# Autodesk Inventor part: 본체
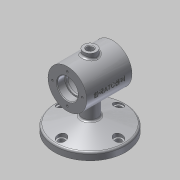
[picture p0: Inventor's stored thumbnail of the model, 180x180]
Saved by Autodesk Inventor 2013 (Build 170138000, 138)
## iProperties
Created: 2018-12
Part Number: 본체
Material: 알루미늄 6061
Document SubType Name: Modeling
Designer: Gpr
Density: 2.71 g/cm^3
Mass: 687.623 g
Surface Area: 555.481 cm^2
Volume: 253.735 cm^3
Author: Gpr
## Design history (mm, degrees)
sketch "스케치1"
  geometry: C1 r 30 at (0, 0); 1 further point
  constraints: 1 centre point, 1 coincident
  dimensions: "d0" = 60 diameter of C1
extrude "돌출1" new body sketch "스케치1" distance "d2" = 35; taper "d3" = 0 deg
sketch "스케치2"
  geometry: C1 r 30 at (0, 0) reference; C2 r 25 at (0, 0)
  constraints: 1 centre point, 1 coincident
  dimensions: "d5" = 50 diameter of C2
extrude "돌출2" cut sketch "스케치2" distance "d7" = 20; taper "d8" = 0 deg
hole "구멍1" diameter "d11" = 28; stored, may be unused: countersink angle "d15" = 90 deg, drill point angle "d17" = 0 deg; dims "d9" = 10, "d10" = 10, "d12" = 6, "d13" = 32, "d14" = 12, "d16" = 8
chamfer "모따기1" distance "d18" = 1; stored, may be unused: second distance "d19" = 2, angle "d20" = 45 deg
fillet "모깎기1" dims "d21" = 3
fillet "모깎기2" dims "d22" = 0.3
sketch "스케치3"
  geometry: C1 r 30 at (0, 0) reference; 1 further point
  constraints: 1 vertical alignment
  dimensions: "d23" = 23 distance of C1.centre point (0, 23)
hole "구멍2" sketch "스케치3" at (0, 23) diameter "d24" = 3.242; stored, may be unused: countersink angle "d28" = 90 deg, drill point angle "d30" = 118 deg; dims "d25" = 8, "d26" = 32, "d27" = 12, "d29" = 10
node "작업 평면1"
sketch "스케치4"
  geometry: C1 r 10 at (0, 0); 1 further point
  constraints: 1 centre point, 1 coincident
  dimensions: "d35" = 20 diameter of C1
extrude "돌출3" join sketch "스케치4" stored distance "d37" = 20; taper "d38" = 0 deg
hole "구멍3" diameter "d41" = 10; stored, may be unused: countersink angle "d45" = 90 deg, drill point angle "d47" = 0 deg; dims "d39" = 10, "d40" = 10, "d42" = 8, "d43" = 32, "d44" = 12, "d46" = 10
chamfer "모따기2" distance "d48" = 1; stored, may be unused: second distance "d49" = 2, angle "d50" = 45 deg
node "작업 평면3"
sketch "스케치5"
  geometry: C1 r 55 at (0, 0); 1 further point
  constraints: 1 centre point, 1 coincident
  dimensions: "d53" = 110 diameter of C1
extrude "돌출4" join sketch "스케치5" distance "d55" = 11; taper "d56" = 0 deg
sketch "스케치6"
  geometry: C1 r 55 at (0, 0) reference; C2 r 12 at (0, 0)
  constraints: 1 centre point, 1 coincident
  dimensions: "d57" = 24 diameter of C2
extrude "돌출5" join sketch "스케치6" stored distance "d59" = 11; taper "d60" = 0 deg
sketch "스케치7"
  geometry: L1 (-75, 55)-(-64, 55) reference; L2 (-64, 12)-(-30, 12) reference; L3 (-52.478, 12)-(-64, 55); L4 (-64, 55)-(-64, 12); L5 (-52.478, 12)-(-64, 12); L6 (-97.4, 0)-(59.4, 0) reference; 1 further point
  constraints: 6 end point, 2 perpendicular, 1 point on line
  dimensions: "d63" = 75 deg angle of L3 L1
revolve "회전1" sketch "스케치7" stored, may be unused: angle "d64" = 90 deg
node "작업 평면4"
sketch "스케치8"
  geometry: 2 further points
  constraints: 1 vertical alignment
  dimensions: "d66" = 44 distance of point (0, 0) point (0, 44)
hole "구멍4" sketch "스케치8" at (0, 44) diameter "d67" = 9; stored, may be unused: countersink angle "d71" = 90 deg, drill point angle "d73" = 0 deg; dims "d68" = 8, "d69" = 14, "d70" = 7, "d72" = 10
fillet "모깎기3" dims "d77" = 3
node "작업 평면5"
sketch "스케치9"
  geometry: L1 (30, 35)-(-30, 35) reference; 2 further points
  constraints: 1 other
  dimensions: "d79" = 35 distance from line of L1 point (0, 0); "d80" = 30 horizontal distance of L1.start point (0, 0)
feature "엠보싱1" sketch "스케치9" dims "d22" = 0.3, "d81" = 0.5, "d82" = 0
node "솔리드1"
pattern_circular "원형 패턴1" dims angle "d32" = 360 deg
mirror "대칭1"
pattern_circular "원형 패턴2" dims angle "d75" = 360 deg
other parameters: "d34" = 37, "d52" = -75, "d65" = -58
